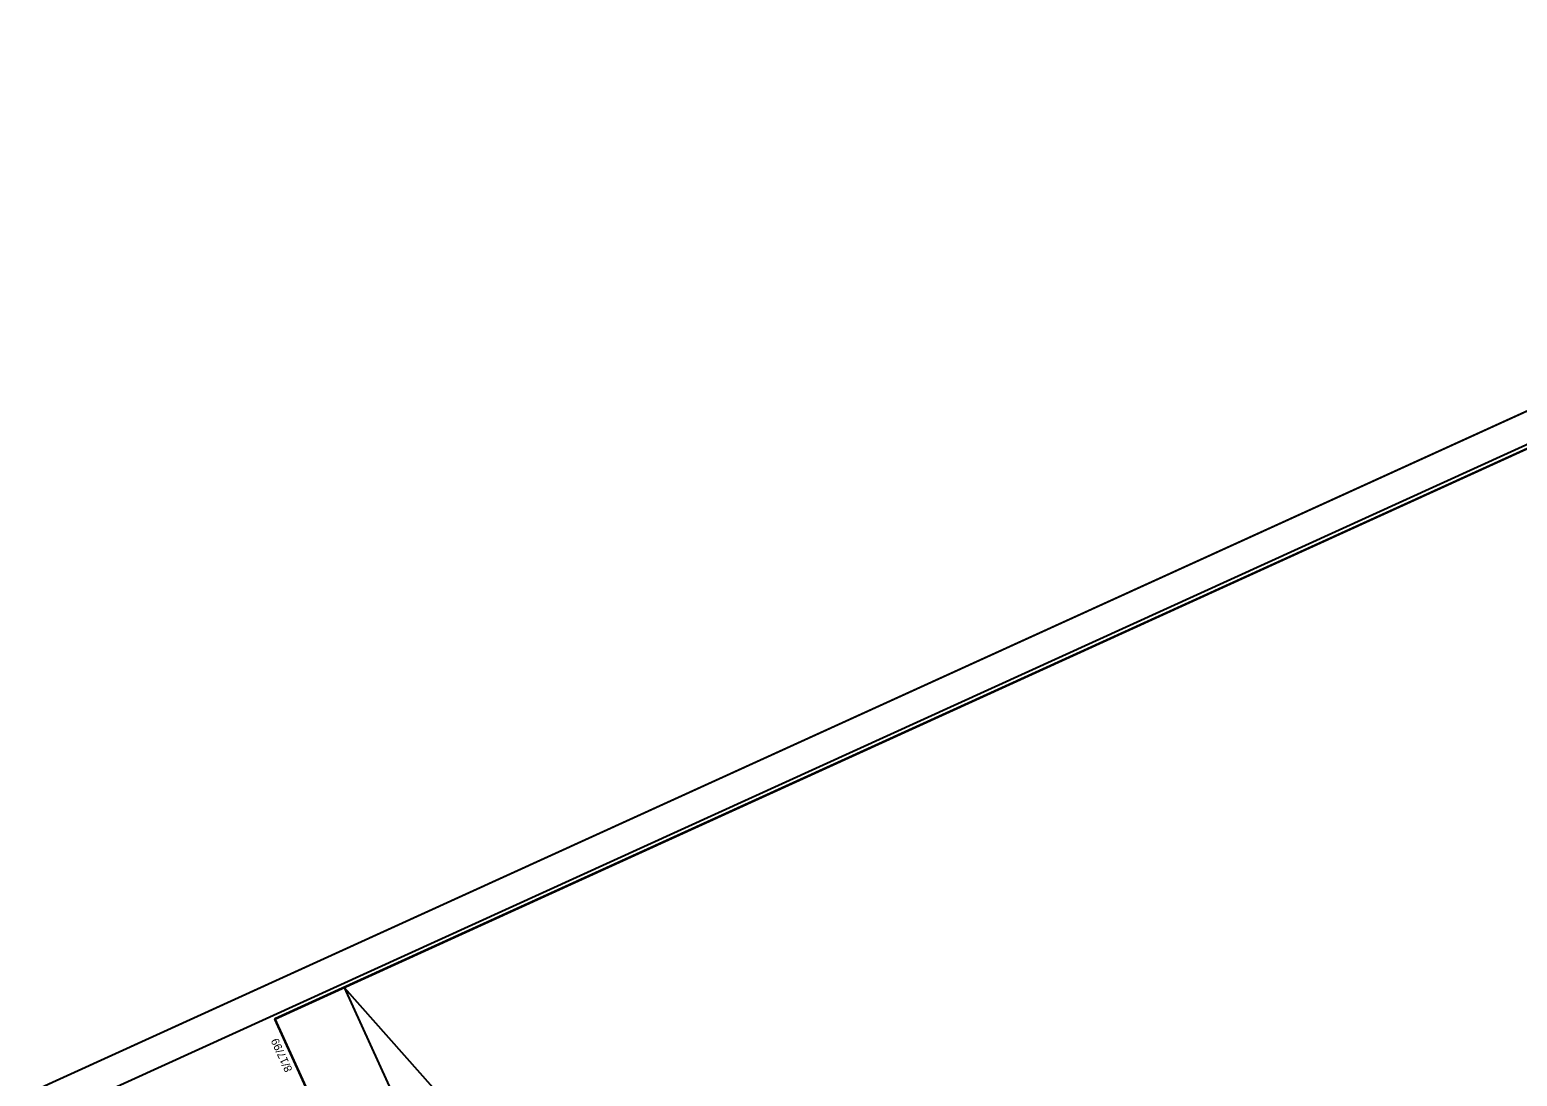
# Model space of a CAD drawing. Extents: x 2249019 to 2251039, y 663030 to 664799.
# Drawn here: x 2249053 to 2250029, y 664038 to 664725 of the extents above; entities that cross this region are included whole.
import ezdxf

# ---------------------------------------------------------------- set-up
doc = ezdxf.new("R2010")
doc.units = 0
for name, color, linetype in [('Sheet Clip Boundary CELL', 7, 'Continuous'), ('Sheet Cutting Line CELL', 7, 'Continuous'), ('Sheet Layout Plan Border', 7, 'Continuous'), ('Sheet Plan CELL', 7, 'Continuous'), ('Sheet Plan Layout CELL', 7, 'Continuous'), ('Sheet Plot Border Inside CELL', 7, 'Continuous'), ('Sheet Plot Border Outside CELL', 7, 'Continuous')]:
    doc.layers.add(name, color=color, linetype=linetype)

msp = doc.modelspace()

# ---------------------------------------------------------------- linework, layer by layer
at = {"layer": 'Sheet Clip Boundary CELL'}
msp.add_lwpolyline([(2249425.27, 663908.72), (2249673.42, 663362.44), (2249790.02, 663300.88), (2249798.45, 663191.7), (2249694.77, 663140.6), (2250968.75, 663721.13), (2250621.05, 664484.16), (2250448.83, 664405.68), (2250361.13, 664598.13), (2249259.38, 664096.08)], close=True, dxfattribs=at)
at = {"layer": 'Sheet Cutting Line CELL'}
msp.add_line((2250585, 664724.85), (2249053.06, 664026.77), dxfattribs=at)
at = {"layer": 'Sheet Layout Plan Border'}
msp.add_lwpolyline([(2249694.77, 663140.6), (2250968.75, 663721.13), (2250621.05, 664484.16), (2250448.83, 664405.68), (2250361.13, 664598.13), (2249259.38, 664096.08)], close=True, dxfattribs=at)
at = {"layer": 'Sheet Plan CELL'}
msp.add_line((2249213.88, 664075.35), (2249213.88, 664075.35), dxfattribs=at)
for points in [[(2250578.88, 664697.35), (2249213.88, 664075.35), (2249649.27, 663119.87), (2251014.25, 663741.87)], [(2249649.27, 663119.87), (2249213.87, 664075.31), (2250396.81, 664614.4), (2250459.05, 664477.85), (2250641.08, 664560.79), (2251014.25, 663741.87)]]:
    msp.add_lwpolyline(points, close=True, dxfattribs=at)
at = {"layer": 'Sheet Plan Layout CELL'}
msp.add_lwpolyline([(2249213.87, 664075.31), (2249649.27, 663119.87), (2251014.24, 663741.86), (2250666.54, 664504.89), (2250448.83, 664405.68), (2250361.13, 664598.13)], close=True, dxfattribs=at)
at = {"layer": 'Sheet Plot Border Inside CELL'}
msp.add_lwpolyline([(2249510.65, 663053.94), (2251026.65, 663744.77), (2250589.2, 664704.79), (2249073.18, 664013.96)], close=True, dxfattribs=at)
at = {"layer": 'Sheet Plot Border Outside CELL'}
msp.add_lwpolyline([(2249507.11, 663030.35), (2251039.05, 663728.43), (2250585, 664724.85), (2249053.06, 664026.77)], close=True, dxfattribs=at)

# ---------------------------------------------------------------- texts
at = {"layer": 'Sheet Plan CELL'}
msp.add_text('8/17/99', height=5.25, rotation=114.49795, dxfattribs=at).set_placement((2249225.55, 664041.95))

doc.saveas('drawing.dxf')
